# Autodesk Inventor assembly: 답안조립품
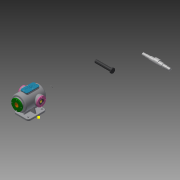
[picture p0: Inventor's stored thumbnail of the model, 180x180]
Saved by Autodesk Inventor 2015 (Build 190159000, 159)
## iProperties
Created: 2021-11
Part Number: 답안조립품
Document SubType Name: Assembly
Designer: now
Author: now
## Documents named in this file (14)
- C:\Users\now\Desktop\711106V1014\답안조립품.iam
- C:\Users\now\Desktop\711106V1014\베어링 6205.ipt
- 베어링 6205.ipt
- C:\Users\now\Desktop\711106V1014\본체.ipt
- C:\Users\now\Desktop\711106V1014\볼트 M4x0.7.ipt
- C:\Users\now\Desktop\711106V1014\부시.ipt
- C:\Users\now\Desktop\711106V1014\상부커버.ipt
- C:\Users\now\Desktop\711106V1014\슬라이드 커버.ipt
- C:\Users\now\Desktop\711106V1014\슬라이드.ipt
- C:\Users\now\Desktop\711106V1014\오일실.ipt
- 오일실.ipt
- C:\Users\now\Desktop\711106V1014\육각머리볼트 M4.ipt
- C:\Users\now\Desktop\711106V1014\축 커버.ipt
- C:\Users\now\Desktop\711106V1014\편심축.ipt
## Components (5 placed, 1 different names)
1. M4x0.7:2
2. M4x0.7:1
3. M4x0.7:3
4. M4x0.7:4
5. M4x0.7:5
